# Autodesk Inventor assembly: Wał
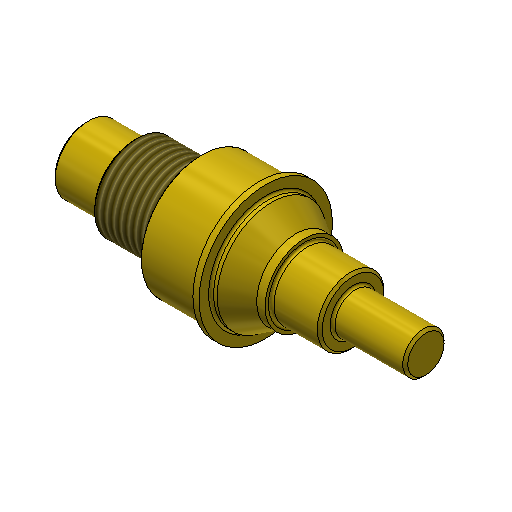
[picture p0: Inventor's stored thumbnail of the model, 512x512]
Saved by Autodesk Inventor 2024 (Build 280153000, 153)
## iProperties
Company: ATC
ClientObjectVersion: 1
Created: 2023-03
Part Number: Wał
Document SubType Name: Assembly
Designer: Andrzej Jaskulski
Checked By: A.J.
Engr Approved By: Andrzej Jaskulski
Mfg Approved By: Andrzej Jaskulski
Authority: A.J.
Title: A.J.: Kurs R2024-MEP
Author: Andrzej Jaskulski
Revision Number: 1/24
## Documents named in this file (2)
- C:\Users\AndJas\Documents\R2024-MEP\Obszar roboczy\PZ\PZ-Dane\Design Accelerator\Wał2.iam
- C:\Users\AndJas\Documents\R2024-MEP\Obszar roboczy\PZ\PZ-Dane\Design Accelerator\Wał2.ipt
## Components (1 placed, 1 different names)
1. Wał:1
